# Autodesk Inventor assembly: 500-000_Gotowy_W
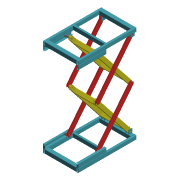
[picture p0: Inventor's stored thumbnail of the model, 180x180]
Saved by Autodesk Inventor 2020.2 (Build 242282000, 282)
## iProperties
Created: 2016-09
Part Number: 500-000_Gotowy_W
Document SubType Name: Assembly
Designer: F.Stasiak
Manager: www.cadconsulting.pl
Company: Fabian Stasiak CAD Consulting
Author: F.Stasiak
Subject: Zbiór ćwiczeń. Autodesk Inventor 2020. Kurs podstawowy
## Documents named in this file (7)
- C:\2020_Kurs_podstawowy\R6 Zespoły\Warsztat\Gotowe\500-000_Gotowy_W.iam
- C:\2020_Kurs_podstawowy\R6 Zespoły\Warsztat\Komponenty\500-05-01.ipt
- C:\2020_Kurs_podstawowy\R6 Zespoły\Warsztat\Komponenty\500-06-01.ipt
- C:\2020_Kurs_podstawowy\R6 Zespoły\Warsztat\Komponenty\500-001_Gotowy_W.iam
- C:\2020_Kurs_podstawowy\R6 Zespoły\Warsztat\Komponenty\500-004_Gotowy_W.iam
- C:\2020_Kurs_podstawowy\R6 Zespoły\Warsztat\Komponenty\500-003_Gotowy_W.iam
- C:\2020_Kurs_podstawowy\R6 Zespoły\Warsztat\Komponenty\500-002_Gotowy_W.iam
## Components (12 placed, 6 different names)
1. 500-001_Gotowy_W:1 [sub-assembly] — PODNIESIENIE, Zestawiający:1, Równoległy:1, Równoległy:2, Wstaw:1, Styczny:1
2. 500-002_Gotowy_W:1 [sub-assembly] — Równoległy:1, Równoległy:2, PODNIESIENIE, Wstaw:3, Zestawiający:3
3. 500-003_Gotowy_W:1 [sub-assembly] — Wstaw:9, Wstaw:10, Wstaw:11
4. 500-003_Gotowy_W:2 [sub-assembly] — Wstaw:4, Wstaw:5, Wstaw:6
5. 500-004_Gotowy_W:1 [sub-assembly] — Zestawiający:1, Wstaw:1, Wstaw:2, Wstaw:5, Wstaw:10, Wstaw:12
6. 500-004_Gotowy_W:2 [sub-assembly] — Wstaw:6, Zestawiający:2, Wstaw:7, Wstaw:8, Wstaw:11, Wstaw:13
7. 500-003_Gotowy_W:3 [sub-assembly] — Wstaw:2, Wstaw:3, Zestawiający:2
8. 500-003_Gotowy_W:4 [sub-assembly] — Wstaw:12, Wstaw:13, Zestawiający:3
9. 500-05-01:1 — Wstaw:9
10. 500-05-01:2 — Wstaw:4, Styczny:1
11. 500-06-01:1 — Wstaw:7
12. 500-06-01:2 — Wstaw:8
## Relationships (20: Insert 13, Flush 3, Mate 3, Tangent 1)
- PODNIESIENIE [Flush]: 500-001_Gotowy_W:1 ↔ 500-002_Gotowy_W:1
- Zestawiający:1 [Mate]: 500-001_Gotowy_W:1 ↔ 500-004_Gotowy_W:1
- Równoległy:1 [Flush]: 500-001_Gotowy_W:1 ↔ 500-002_Gotowy_W:1
- Równoległy:2 [Flush]: 500-001_Gotowy_W:1 ↔ 500-002_Gotowy_W:1
- Wstaw:1 [Insert]: 500-001_Gotowy_W:1 ↔ 500-004_Gotowy_W:1
- Wstaw:2 [Insert]: 500-004_Gotowy_W:1 ↔ 500-003_Gotowy_W:3
- Wstaw:3 [Insert]: 500-002_Gotowy_W:1 ↔ 500-003_Gotowy_W:3
- Wstaw:4 [Insert]: 500-003_Gotowy_W:2 ↔ 500-05-01:2
- Wstaw:5 [Insert]: 500-003_Gotowy_W:2 ↔ 500-004_Gotowy_W:1
- Styczny:1 [Tangent]: 500-001_Gotowy_W:1 ↔ 500-05-01:2
- Wstaw:6 [Insert]: 500-003_Gotowy_W:2 ↔ 500-004_Gotowy_W:2
- Zestawiający:2 [Mate]: 500-004_Gotowy_W:2 ↔ 500-003_Gotowy_W:3
- Wstaw:7 [Insert]: 500-004_Gotowy_W:2 ↔ 500-06-01:1
- Wstaw:8 [Insert]: 500-004_Gotowy_W:2 ↔ 500-06-01:2
- Wstaw:9 [Insert]: 500-003_Gotowy_W:1 ↔ 500-05-01:1
- Wstaw:10 [Insert]: 500-003_Gotowy_W:1 ↔ 500-004_Gotowy_W:1
- Wstaw:11 [Insert]: 500-003_Gotowy_W:1 ↔ 500-004_Gotowy_W:2
- Wstaw:12 [Insert]: 500-004_Gotowy_W:1 ↔ 500-003_Gotowy_W:4
- Wstaw:13 [Insert]: 500-004_Gotowy_W:2 ↔ 500-003_Gotowy_W:4
- Zestawiający:3 [Mate]: 500-002_Gotowy_W:1 ↔ 500-003_Gotowy_W:4
